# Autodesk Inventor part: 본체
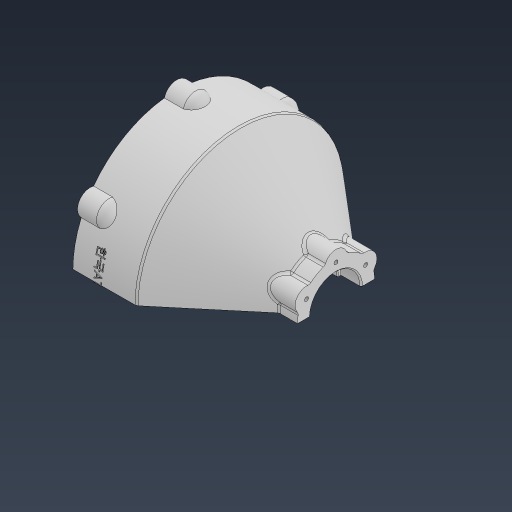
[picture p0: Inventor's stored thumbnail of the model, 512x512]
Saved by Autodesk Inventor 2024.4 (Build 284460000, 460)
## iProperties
Created: 2026-05
Part Number: 본체
Material: 일반
Document SubType Name: Modeling
Designer: user
Density: 1 g/cm^3
Appearance: 기본값
Author: user
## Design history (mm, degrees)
sketch "스케치1"
  geometry: L1 (0, 0)-(0, 82); L2 (0, 82)-(50, 82); L3 (50, 82)-(111.375, 30.5); L4 (111.375, 30.5)-(126, 30.5); L5 (126, 30.5)-(126, 0); L6 (126, 0)-(0, 0); L7 (0, 73)-(37, 73); L8 (37, 73)-(37, 68); L9 (37, 68)-(42, 68); L10 (42, 68)-(42, 56); L11 (42, 56)-(62, 56); L12 (62, 56)-(62, 40); L13 (62, 40)-(78, 40); L14 (78, 40)-(78, 37); L15 (78, 37)-(82, 37); L16 (82, 37)-(82, 20); L17 (82, 20)-(94, 20); L18 (94, 20)-(94, 17.5); L19 (94, 17.5)-(110, 17.5); L20 (110, 17.5)-(110, 20); L21 (110, 20)-(126, 20); 1 further point
  constraints: 42 end point, 17 perpendicular, 2 point on line, 2 vertical, 1 midpoint, 1 parallel
  dimensions: "d0" = 164 diameter of L2 L6; "d1" = 126 distance between parallel lines of L5 L1; "d2" = 50 distance of L1.end L2.end; "d3" = 40 deg angle of L3 L2; "d4" = 61 diameter of L4 L6; "d5" = 37 distance of L7.start L7.end; "d6" = 146 diameter of L7 L6; "d7" = 5 distance of L8.end L9.end; "d8" = 136 diameter of L9 L6; "d9" = 25 distance from line of point (62, 48) L8; "d10" = 112 diameter of L11 L6; "d11" = 16 distance of L12.end L13.end; "d12" = 4 distance of L14.end L15.end; "d13" = 80 diameter of L13 L6; "d14" = 74 diameter of L15 L6; "d15" = 40 diameter of L17 L6; "d16" = 40 diameter of L21 L6; "d17" = 35 diameter of L19 L6; "d18" = 12 distance of L16.end L17.end; "d19" = 16 distance of L20.end L21.end
revolve "회전1" sketch "스케치1" stored, may be unused: angle "d20" = 90 deg
sketch "스케치2" dims "d24" = 54
  geometry: L1 (0, 0)-(0, 94.338); L2 (0, 0)-(-67.233, 38.817); C1 r 30.5 at (0, 0) reference; A1 r 20 centre (0, 0) between (-19.224, 5.519) and (-14.391, 13.889) reference; A2 r 9 centre (-23.383, 13.5) between (-14.391, 13.889) and (-19.224, 5.519); A3 r 20 centre (0, 0) between (-14.391, 13.889) and (-19.224, 5.519); 1 further point
  constraints: 6 point on circle, 4 end point, 2 centre point, 2 coincident, 1 concentric, 1 point on line, 1 vertical, 3 other
  dimensions: "d21" = 60 deg angle of L2 L1; "d23" = 18 diameter of A2
sketch "스케치4" dims "d39" = 124
  geometry: L1 (0, 0)-(0, -112.084); L2 (0, 0)-(98.539, -56.892); C1 r 68 at (0, 0) reference; 1 further point
  constraints: 4 end point, 1 coincident, 1 point on line, 1 vertical, 1 vertical alignment, 2 other
  dimensions: "d40" = 60 deg angle of L1 L2
hole "구멍2" sketch "스케치4" at (0, -62) diameter "d41" = 3.242; stored, may be unused: countersink angle "d45" = 90 deg, drill point angle "d47" = 118 deg; dims "d42" = 8, "d43" = 4, "d44" = 2, "d46" = 10
sketch "스케치5" dims "d51" = 158
  geometry: L1 (0, 0)-(0, -139.331); L2 (0, 0)-(112.907, -65.187); C1 r 82 at (0, 0) reference; 1 further point
  constraints: 4 end point, 1 coincident, 1 point on line, 1 vertical, 1 vertical alignment, 2 other
  dimensions: "d52" = 60 deg angle of L1 L2
hole "구멍3" sketch "스케치5" at (0, -79) diameter "d53" = 4.917; stored, may be unused: countersink angle "d57" = 90 deg, drill point angle "d59" = 118 deg; dims "d54" = 12, "d55" = 4, "d56" = 2, "d58" = 14
sketch "스케치6" dims "d63" = 153.0712
  geometry: L1 (0, 0)-(-38.268, -66.282); C1 r 2.458 at (0, -79) reference; C2 r 73 at (0, 0) reference; C3 r 82 at (0, 0) reference; C4 r 1.621 at (-23.383, -13.5) reference; C5 r 10 at (0, -79); 3 further points
  constraints: 2 coincident, 2 end point, 1 centre point, 1 point on line, 3 other
  dimensions: "d65" = 20 diameter of C5
extrude "돌출2" join sketch "스케치6" distance "d66" = 15; taper "d67" = 0 deg
sketch "스케치7"
  geometry: L1 (9.702, -81.424)-(-9.702, -81.424); A1 r 10 centre (0, -79) between (-9.702, -81.424) and (9.702, -81.424) reference
  constraints: 2 end point, 1 horizontal
revolve "회전2" sketch "스케치7" stored, may be unused: angle "d68" = 90 deg
extrude "돌출3" join sketch "스케치2" stored distance "d72" = 15; taper "d73" = 0 deg
hole "구멍4" sketch "스케치2" diameter "d77" = 3.242; stored, may be unused: countersink angle "d81" = 90 deg, drill point angle "d83" = 118 deg; dims "d78" = 8, "d79" = 4, "d80" = 2, "d82" = 10
chamfer "모따기1" distance "d87" = 1; stored, may be unused: second distance "d88" = 2, angle "d89" = 45 deg
fillet "모깎기1" dims "d90" = 3
chamfer "모따기2" distance "d91" = 1; stored, may be unused: second distance "d92" = 2, angle "d93" = 45 deg
fillet "모깎기2" dims "d94" = 3
chamfer "모따기3" distance "d95" = 1; stored, may be unused: second distance "d96" = 2, angle "d97" = 45 deg
fillet "모깎기3" dims "d98" = 1
fillet "모깎기4" dims "d99" = 3
chamfer "모따기4" distance "d100" = 1; stored, may be unused: second distance "d101" = 2, angle "d102" = 45 deg
chamfer "모따기5" distance "d103" = 1; stored, may be unused: second distance "d104" = 2, angle "d105" = 45 deg
fillet "모깎기5" dims "d106" = 0.6
chamfer "모따기6" distance "d107" = 1; stored, may be unused: second distance "d108" = 2, angle "d109" = 45 deg
fillet "모깎기6" dims "d110" = 3
sketch "스케치8" dims "d0" = 164, "d1" = 126, "d2" = 50, "d3" = 40 deg, "d4" = 61, "d5" = 37, "d6" = 146, "d7" = 5, "d8" = 136, "d9" = 25, "d10" = 112, "d11" = 16, "d12" = 4, "d13" = 80, "d14" = 74, "d15" = 40, "d16" = 40, "d17" = 35, "d18" = 12, "d19" = 16
  geometry: L1 (0, 32.31)-(0, -32.31) reference; 4 further points
  constraints: 2 midpoint, 1 horizontal alignment, 1 other
  dimensions: "d111" = 20 distance of point (20, 0) point (0, 0)
feature "엠보싱1" sketch "스케치8" dims "d0" = 164, "d1" = 126, "d2" = 50, "d3" = 40 deg, "d4" = 61, "d5" = 37, "d6" = 146, "d7" = 5, "d8" = 136, "d9" = 25, "d10" = 112, "d11" = 16, "d12" = 4, "d13" = 80, "d14" = 74, "d15" = 40, "d16" = 40, "d17" = 35, "d18" = 12, "d19" = 16, "d112" = 0.5, "d113" = 0
sketch "스케치9"
  geometry: A1 r 10 centre (68.416, 118.5) between (75.366, 111.31) and (65.664, 128.114) reference; 2 further points
  constraints: 1 coincident
hole "구멍5" sketch "스케치9" at (68.416, 118.5) diameter "d114" = 4.917; stored, may be unused: countersink angle "d118" = 90 deg, drill point angle "d120" = 118 deg; dims "d115" = 12, "d116" = 4, "d117" = 2, "d119" = 17.1
node "솔리드1"
pattern_circular "원형 패턴2" dims angle "d49" = 360 deg
pattern_circular "원형 패턴3" dims angle "d61" = 360 deg
pattern_circular "원형 패턴4" dims angle "d70" = 360 deg
pattern_circular "원형 패턴5" dims angle "d75" = 360 deg
pattern_circular "원형 패턴6" dims angle "d85" = 360 deg
pattern_circular "원형 패턴7" dims angle "d122" = 360 deg
feature "A9D066F2-1C7D-4E18-AEED-F7BC21143FA4" dims "d53" = 4.917, "d54" = 12, "d55" = 4, "d56" = 2, "d57" = 90 deg, "d58" = 14, "d59" = 118 deg
